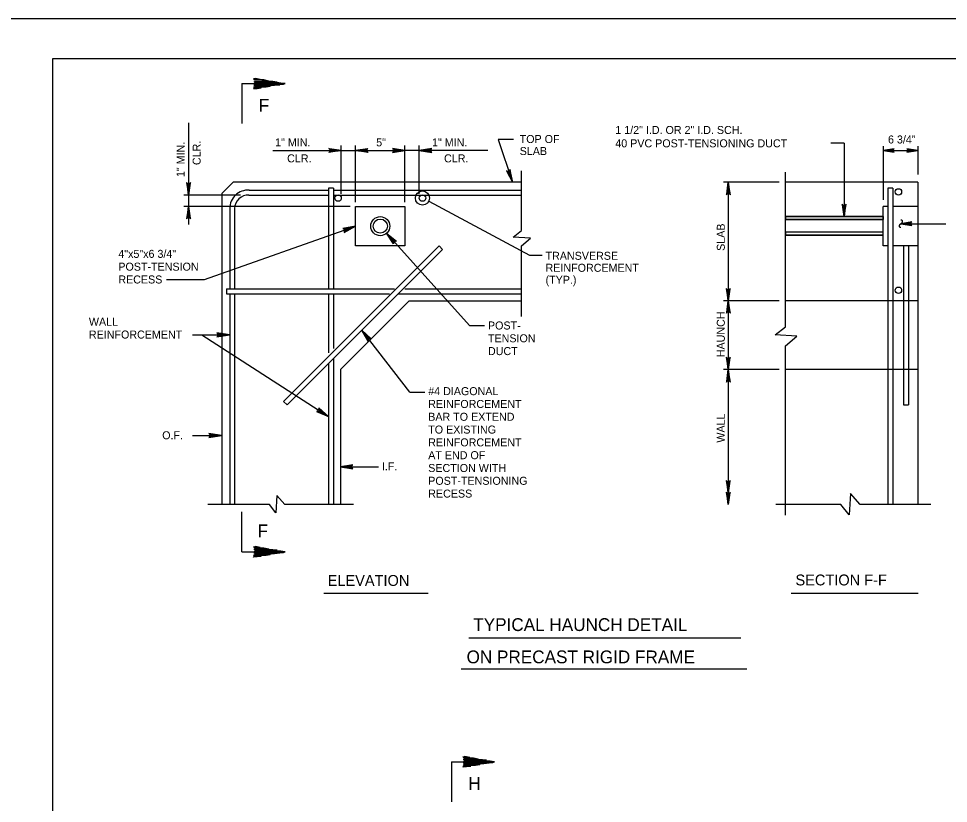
# Model space of a CAD drawing. Extents: x 641328 to 643024, y 298283 to 300065.
# Drawn here: x 642195.6 to 642544.1, y 299771.1 to 300065.3 of the extents above; entities that cross this region are included whole.
import ezdxf

# ---------------------------------------------------------------- set-up
doc = ezdxf.new("R2010")
doc.units = 0
for name, color, linetype in [('2', 7, 'Continuous'), ('63', 7, 'Continuous'), ('Default', 7, 'Continuous'), ('PLT-BNDY', 7, 'Continuous'), ('S-ANNO-DIMENSION-PROP', 7, 'Continuous')]:
    doc.layers.add(name, color=color, linetype=linetype)

msp = doc.modelspace()

# ---------------------------------------------------------------- linework, layer by layer
at = {"layer": '2'}
for p, q in [((642208.51, 299486.3), (642208.51, 300050.3)), ((642208.51, 300050.3), (642994.5, 300050.3)), ((642279.3, 300040.96), (642279.3, 300025.93)), ((642279.3, 300040.96), (642294.33, 300040.96)), ((642375.35, 300020.03), (642380.68, 300003.92)), ((642316.56, 299999.64), (642316.56, 300017.73)), ((642321.92, 299996.47), (642321.92, 300017.73)), ((642340.43, 299996.47), (642340.43, 300017.73)), ((642345.78, 299999.64), (642345.78, 300017.73)), ((642505, 300018.56), (642499.99, 300018.56)), ((642519.63, 300015.85), (642532.63, 300015.85)), ((642384.07, 299985.85), (642384.07, 300008.18)), ((642483.06, 299949.79), (642483.06, 300007.67)), ((642383.93, 300003.92), (642276, 300003.92)), ((642480.62, 300003.92), (642459.79, 300003.92)), ((642532.63, 300003.92), (642483.06, 300003.92)), ((642532.63, 300003.92), (642532.63, 299883.1)), ((642278.78, 299999.14), (642257.52, 299999.14)), ((642271.81, 299999.73), (642271.81, 299883.2)), ((642281.94, 299999.14), (642311.75, 299999.14)), ((642282.06, 300000.99), (642311.75, 300000.99)), ((642313.6, 300001.79), (642311.75, 300001.79)), ((642311.75, 300001.79), (642311.75, 299964.24)), ((642313.6, 300001.79), (642313.6, 299964.13)), ((642313.6, 300000.99), (642383.93, 300000.99)), ((642313.6, 299999.14), (642383.93, 299999.14)), ((642523.29, 300001.79), (642521.44, 300001.79)), ((642521.44, 300001.79), (642521.44, 299883.1)), ((642523.29, 300001.79), (642523.29, 299883.1)), ((642349.39, 299996.89), (642387.06, 299976.65)), ((642319.93, 299994.9), (642257.52, 299994.9)), ((642274.74, 299994.1), (642274.74, 299963.94)), ((642276.59, 299994.1), (642276.59, 299963.94)), ((642519.63, 299980.08), (642519.63, 299994.9)), ((642521.44, 299994.9), (642519.63, 299994.9)), ((642532.63, 299994.9), (642523.29, 299994.9)), ((642519.63, 299991.06), (642483.06, 299991.06)), ((642519.63, 299989.95), (642483.06, 299989.95)), ((642526.27, 299988.4), (642543.14, 299988.4)), ((642265.29, 299967.54), (642321.92, 299987.49)), ((642519.63, 299985.23), (642483.06, 299985.23)), ((642364.57, 299950.22), (642333.56, 299984.83)), ((642519.63, 299984.11), (642483.06, 299984.11)), ((642354.54, 299978.77), (642296.22, 299920.45)), ((642353.23, 299980.08), (642306.4, 299933.26)), ((642354.54, 299978.77), (642353.23, 299980.08)), ((642384.07, 299953.63), (642384.07, 299980.06)), ((642521.44, 299980.08), (642519.63, 299980.08)), ((642532.63, 299980.08), (642523.29, 299980.08)), ((642527.27, 299980.08), (642527.27, 299920.45)), ((642529.12, 299980.08), (642529.12, 299920.45)), ((642387.06, 299976.65), (642391.88, 299976.65)), ((642251.08, 299967.54), (642265.29, 299967.54)), ((642273.6, 299963.94), (642273.6, 299962.09)), ((642273.6, 299963.94), (642336.52, 299963.94)), ((642340.36, 299963.94), (642383.93, 299963.94)), ((642273.6, 299962.09), (642334.59, 299962.09)), ((642274.74, 299962.09), (642274.74, 299883.2)), ((642276.59, 299962.09), (642276.59, 299883.2)), ((642311.75, 299961.91), (642311.75, 299939.99)), ((642313.6, 299962.02), (642313.6, 299941.62)), ((642338, 299962.09), (642383.93, 299962.09)), ((642342.03, 299959.48), (642316.25, 299933.7)), ((642342.03, 299959.48), (642384.07, 299959.48)), ((642480.62, 299959.48), (642459.79, 299959.48)), ((642532.63, 299959.48), (642483.06, 299959.48)), ((642364.57, 299950.22), (642370.21, 299950.22)), ((642260.77, 299946.73), (642274.74, 299946.73)), ((642264.26, 299946.73), (642311.75, 299916.09)), ((642342.2, 299925.28), (642324.24, 299948.47)), ((642483.06, 299879.16), (642483.06, 299942.68)), ((642313.6, 299937.77), (642313.6, 299883.2)), ((642294.91, 299921.76), (642306.4, 299933.26)), ((642311.75, 299935.85), (642311.75, 299883.2)), ((642316.25, 299933.7), (642316.25, 299883.2)), ((642480.62, 299933.7), (642459.79, 299933.7)), ((642532.63, 299933.7), (642483.06, 299933.7)), ((642342.2, 299925.28), (642347.84, 299925.28)), ((642296.22, 299920.45), (642294.91, 299921.76)), ((642260.77, 299908.99), (642271.81, 299908.99)), ((642316.25, 299897.31), (642330.5, 299897.31)), ((642289.6, 299883.1), (642266.57, 299883.1)), ((642279.3, 299865.34), (642279.3, 299880.37)), ((642321.1, 299883.1), (642295.39, 299883.1)), ((642503.84, 299883.1), (642479.45, 299883.1)), ((642537.48, 299883.1), (642510.99, 299883.1)), ((642279.3, 299865.34), (642294.33, 299865.34)), ((642349.08, 299849.76), (642310.05, 299849.76)), ((642532.77, 299849.76), (642485.16, 299849.76)), ((642364.3, 299833.15), (642466.25, 299833.15)), ((642361.48, 299821.51), (642468.57, 299821.51)), ((642357.81, 299786.73), (642357.81, 299771.7)), ((642357.81, 299786.73), (642372.84, 299786.73))]:
    msp.add_line(p, q, dxfattribs=at)
for points in [[(642283.61, 300042.89), (642295.49, 300040.91), (642283.61, 300038.93), (642283.8, 300039.12), (642284.99, 300039.12), (642286.58, 300039.32), (642283.8, 300039.32), (642284, 300039.72), (642288.36, 300039.72), (642289.94, 300039.92), (642284, 300039.92), (642284, 300040.31), (642291.53, 300040.31), (642293.51, 300040.51), (642284, 300040.51), (642284, 300040.71), (642294.89, 300040.71), (642295.49, 300040.91), (642293.9, 300041.1), (642284.2, 300041.1), (642284, 300041.3), (642292.52, 300041.5), (642290.93, 300041.7), (642284, 300041.7), (642284, 300041.9), (642289.35, 300041.9), (642287.57, 300042.29), (642284, 300042.29), (642283.8, 300042.49), (642286.18, 300042.49), (642284.4, 300042.89), (642283.8, 300042.69)], [(642523.55, 300016.35), (642523.4, 300016.06), (642519.63, 300015.85), (642523.55, 300016.35), (642523.75, 300016.52), (642519.63, 300015.85), (642523.4, 300015.67), (642523.54, 300015.39), (642519.63, 300015.85), (642523.75, 300015.2), (642523.54, 300015.39)], [(642528.7, 300015.36), (642528.85, 300015.65), (642532.63, 300015.85), (642528.7, 300015.36), (642528.5, 300015.19), (642532.63, 300015.85), (642528.85, 300016.04), (642528.72, 300016.32), (642532.63, 300015.85), (642528.5, 300016.51), (642528.72, 300016.32)], [(642378.68, 300008.12), (642379.05, 300008.06), (642380.68, 300003.92), (642378.68, 300008.12), (642378.42, 300008.28), (642380.68, 300003.92), (642379.5, 300008.21), (642379.76, 300008.46), (642380.68, 300003.92), (642379.89, 300008.77), (642379.76, 300008.46)], [(642530.19, 299988.89), (642530.04, 299988.6), (642526.27, 299988.4), (642530.19, 299988.89), (642530.39, 299989.06), (642526.27, 299988.4), (642530.04, 299988.21), (642530.18, 299987.93), (642526.27, 299988.4), (642530.39, 299987.74), (642530.18, 299987.93)], [(642317.76, 299985.4), (642317.81, 299985.77), (642321.92, 299987.49), (642317.76, 299985.4), (642317.61, 299985.13), (642321.92, 299987.49), (642317.66, 299986.21), (642317.4, 299986.46), (642321.92, 299987.49), (642317.09, 299986.59), (642317.4, 299986.46)], [(642270.12, 299946.15), (642270.29, 299946.48), (642274.74, 299946.73), (642270.12, 299946.15), (642269.89, 299945.95), (642274.74, 299946.73), (642270.3, 299946.95), (642270.14, 299947.28), (642274.74, 299946.73), (642269.89, 299947.5), (642270.14, 299947.28)], [(642307.56, 299918.11), (642307.89, 299918.29), (642311.75, 299916.09), (642307.56, 299918.11), (642307.25, 299918.06), (642311.75, 299916.09), (642308.14, 299918.68), (642308.18, 299919.05), (642311.75, 299916.09), (642308.09, 299919.37), (642308.18, 299919.05)], [(642267.19, 299908.41), (642267.37, 299908.75), (642271.81, 299908.99), (642267.19, 299908.41), (642266.96, 299908.21), (642271.81, 299908.99), (642267.37, 299909.21), (642267.21, 299909.54), (642271.81, 299908.99), (642266.96, 299909.76), (642267.21, 299909.54)], [(642283.61, 299867.37), (642295.49, 299865.39), (642283.61, 299863.41), (642283.8, 299863.61), (642284.99, 299863.61), (642286.58, 299863.81), (642283.8, 299863.81), (642284, 299864.21), (642288.36, 299864.21), (642289.94, 299864.4), (642284, 299864.4), (642284, 299864.8), (642291.53, 299864.8), (642293.51, 299865), (642284, 299865), (642284, 299865.2), (642294.89, 299865.2), (642295.49, 299865.39), (642293.9, 299865.59), (642284.2, 299865.59), (642284, 299865.79), (642292.52, 299865.99), (642290.93, 299866.19), (642284, 299866.19), (642284, 299866.38), (642289.35, 299866.38), (642287.57, 299866.78), (642284, 299866.78), (642283.8, 299866.98), (642286.18, 299866.98), (642284.4, 299867.37), (642283.8, 299867.18)], [(642362.11, 299788.65), (642373.99, 299786.67), (642362.11, 299784.69), (642362.31, 299784.89), (642363.5, 299784.89), (642365.08, 299785.09), (642362.31, 299785.09), (642362.51, 299785.48), (642366.87, 299785.48), (642368.45, 299785.68), (642362.51, 299785.68), (642362.51, 299786.08), (642370.03, 299786.08), (642372.01, 299786.28), (642362.51, 299786.28), (642362.51, 299786.47), (642373.4, 299786.47), (642373.99, 299786.67), (642372.41, 299786.87), (642362.71, 299786.87), (642362.51, 299787.07), (642371.02, 299787.27), (642369.44, 299787.46), (642362.51, 299787.46), (642362.51, 299787.66), (642367.86, 299787.66), (642366.07, 299788.06), (642362.51, 299788.06), (642362.31, 299788.26), (642364.69, 299788.26), (642362.91, 299788.65), (642362.31, 299788.45)]]:
    msp.add_lwpolyline(points, dxfattribs=at)
for points in [[(642321.92, 299994.9), (642340.43, 299994.9), (642340.43, 299980.08), (642321.92, 299980.08)], [(642519.63, 299989.95), (642483.06, 299989.95), (642483.06, 299991.06), (642519.63, 299991.06)], [(642519.63, 299991.06), (642483.06, 299991.06), (642483.06, 299989.95), (642519.63, 299989.95)], [(642519.63, 299985.23), (642483.06, 299985.23), (642483.06, 299984.11), (642519.63, 299984.11)]]:
    msp.add_lwpolyline(points, close=True, dxfattribs=at)
for centre in [(642315.36, 299998.02), (642346.99, 299998.02), (642525.36, 300000.33), (642525.36, 299963.45)]:
    msp.add_circle(centre, 1.21, dxfattribs=at)
for radius in [6.89, 5.04]:
    msp.add_arc((642281.63, 299994.1), radius, 86.4281, 180, dxfattribs=at)
at = {"layer": '63'}
for p, q in [((642259.35, 300026.25), (642259.35, 299994.9)), ((642505, 300018.56), (642505, 299991.06)), ((642519.63, 300017.46), (642519.63, 299997.36)), ((642532.63, 300017.46), (642532.63, 300006.79)), ((642290.92, 300015.9), (642321.92, 300015.9)), ((642321.92, 300015.9), (642340.43, 300015.9)), ((642371.43, 300015.9), (642340.43, 300015.9)), ((642461.61, 300003.92), (642461.61, 299959.48)), ((642259.35, 299994.9), (642259.35, 299988.14)), ((642380.96, 299983.33), (642384.04, 299985.82)), ((642387.46, 299982.98), (642380.96, 299983.33)), ((642384.07, 299980.06), (642387.46, 299982.98)), ((642461.61, 299959.48), (642461.61, 299933.7)), ((642479.21, 299946.71), (642483.01, 299949.79)), ((642487.23, 299946.29), (642479.21, 299946.71)), ((642483.06, 299942.68), (642487.23, 299946.29)), ((642461.61, 299933.7), (642461.61, 299883.1)), ((642527.27, 299920.45), (642529.12, 299920.45)), ((642507.34, 299887.32), (642506.92, 299879.3)), ((642510.99, 299883.1), (642507.34, 299887.32)), ((642292.43, 299886.52), (642292.09, 299880.02)), ((642295.39, 299883.1), (642292.43, 299886.52)), ((642292.09, 299880.02), (642289.6, 299883.1)), ((642506.92, 299879.3), (642503.84, 299883.1))]:
    msp.add_line(p, q, dxfattribs=at)
for points in [[(642312.13, 300016.45), (642312.3, 300016.13), (642316.56, 300015.9), (642312.13, 300016.45), (642311.91, 300016.65), (642316.56, 300015.9), (642312.3, 300015.69), (642312.15, 300015.37), (642316.56, 300015.9), (642311.91, 300015.16), (642312.15, 300015.37)], [(642326.34, 300015.34), (642326.18, 300015.66), (642321.92, 300015.9), (642326.34, 300015.34), (642326.57, 300015.15), (642321.92, 300015.9), (642326.18, 300016.11), (642326.33, 300016.43), (642321.92, 300015.9), (642326.57, 300016.64), (642326.33, 300016.43)], [(642336, 300015.34), (642336.17, 300015.66), (642340.43, 300015.9), (642336, 300015.34), (642335.78, 300015.15), (642340.43, 300015.9), (642336.17, 300016.11), (642336.02, 300016.43), (642340.43, 300015.9), (642335.78, 300016.64), (642336.02, 300016.43)], [(642350.21, 300016.45), (642350.05, 300016.13), (642345.78, 300015.9), (642350.21, 300016.45), (642350.44, 300016.65), (642345.78, 300015.9), (642350.04, 300015.69), (642350.2, 300015.37), (642345.78, 300015.9), (642350.44, 300015.16), (642350.2, 300015.37)], [(642258.8, 300003.57), (642259.12, 300003.4), (642259.35, 299999.14), (642258.8, 300003.57), (642258.6, 300003.79), (642259.35, 299999.14), (642259.56, 300003.4), (642259.88, 300003.55), (642259.35, 299999.14), (642260.09, 300003.79), (642259.88, 300003.55)], [(642462.17, 299999.5), (642461.85, 299999.66), (642461.61, 300003.92), (642462.17, 299999.5), (642462.37, 299999.27), (642461.61, 300003.92), (642461.4, 299999.66), (642461.09, 299999.51), (642461.61, 300003.92), (642460.88, 299999.27), (642461.09, 299999.51)], [(642504.44, 299995.49), (642504.76, 299995.32), (642505, 299991.06), (642504.44, 299995.49), (642504.25, 299995.72), (642505, 299991.06), (642505.21, 299995.32), (642505.53, 299995.48), (642505, 299991.06), (642505.74, 299995.72), (642505.53, 299995.48)], [(642259.91, 299990.47), (642259.59, 299990.63), (642259.35, 299994.9), (642259.91, 299990.47), (642260.1, 299990.24), (642259.35, 299994.9), (642259.14, 299990.64), (642258.82, 299990.48), (642259.35, 299994.9), (642258.61, 299990.24), (642258.82, 299990.48)], [(642336.11, 299981.17), (642336.24, 299981.5), (642333.56, 299984.83), (642336.11, 299981.17), (642336.12, 299980.87), (642333.56, 299984.83), (642336.57, 299981.8), (642336.91, 299981.9), (642333.56, 299984.83), (642337.22, 299981.86), (642336.91, 299981.9)], [(642461.06, 299963.91), (642461.38, 299963.75), (642461.61, 299959.48), (642461.06, 299963.91), (642460.86, 299964.14), (642461.61, 299959.48), (642461.83, 299963.74), (642462.14, 299963.9), (642461.61, 299959.48), (642462.35, 299964.14), (642462.14, 299963.9)], [(642462.17, 299955.06), (642461.85, 299955.22), (642461.61, 299959.48), (642462.17, 299955.06), (642462.37, 299954.83), (642461.61, 299959.48), (642461.4, 299955.22), (642461.09, 299955.07), (642461.61, 299959.48), (642460.88, 299954.83), (642461.09, 299955.07)], [(642327.4, 299945.32), (642327.05, 299945.26), (642324.24, 299948.47), (642327.4, 299945.32), (642327.7, 299945.27), (642324.24, 299948.47), (642326.69, 299944.99), (642326.54, 299944.67), (642324.24, 299948.47), (642326.52, 299944.35), (642326.54, 299944.67)], [(642461.06, 299938.13), (642461.38, 299937.96), (642461.61, 299933.7), (642461.06, 299938.13), (642460.86, 299938.35), (642461.61, 299933.7), (642461.83, 299937.96), (642462.14, 299938.11), (642461.61, 299933.7), (642462.35, 299938.35), (642462.14, 299938.11)], [(642462.17, 299929.27), (642461.85, 299929.43), (642461.61, 299933.7), (642462.17, 299929.27), (642462.37, 299929.04), (642461.61, 299933.7), (642461.4, 299929.44), (642461.09, 299929.28), (642461.61, 299933.7), (642460.88, 299929.04), (642461.09, 299929.28)], [(642320.68, 299897.87), (642320.51, 299897.55), (642316.25, 299897.31), (642320.68, 299897.87), (642320.9, 299898.06), (642316.25, 299897.31), (642320.51, 299897.1), (642320.66, 299896.78), (642316.25, 299897.31), (642320.9, 299896.57), (642320.66, 299896.78)], [(642461.06, 299891.95), (642461.38, 299891.79), (642461.61, 299887.53), (642461.06, 299891.95), (642460.86, 299892.18), (642461.61, 299887.53), (642461.83, 299891.79), (642462.14, 299891.94), (642461.61, 299887.53), (642462.35, 299892.18), (642462.14, 299891.94)], [(642461.06, 299887.53), (642461.38, 299887.36), (642461.61, 299883.1), (642461.06, 299887.53), (642460.86, 299887.75), (642461.61, 299883.1), (642461.83, 299887.36), (642462.14, 299887.51), (642461.61, 299883.1), (642462.35, 299887.75), (642462.14, 299887.51)]]:
    msp.add_lwpolyline(points, dxfattribs=at)
for centre, radius in [((642346.99, 299998.02), 2.65), ((642331.17, 299987.49), 3.57), ((642331.17, 299987.49), 2.65)]:
    msp.add_circle(centre, radius, dxfattribs=at)
at = {"layer": 'Default'}
for p, q in [((642381.16, 300020.03), (642375.35, 300020.03)), ((642271.81, 299999.73), (642276, 300003.92))]:
    msp.add_line(p, q, dxfattribs=at)
at = {"layer": 'PLT-BNDY'}
msp.add_lwpolyline([(642168.51, 300065.3), (643009.51, 300065.3), (643009.51, 299471.3), (642168.51, 299471.3)], close=True, dxfattribs=at)
at = {"layer": 'S-ANNO-DIMENSION-PROP'}
for q in [(642526.73, 299988.87), (642526.74, 299988.87)]:
    msp.add_line((642525.8, 299987.93), q, dxfattribs=at)
for centre, start, end in [((642526.4, 299989.24), 311.7859, 104.3183), ((642526.41, 299989.23), 311.5891, 104.1215), ((642526.13, 299987.56), 131.7859, 284.3183), ((642526.13, 299987.56), 131.5891, 284.1215)]:
    msp.add_arc(centre, 0.494, start, end, dxfattribs=at)

# ---------------------------------------------------------------- texts
at = {"layer": '2'}
for s, height, p in [('F', 4.8, (642285.62, 300030.39)), ('1 1/2" I.D. OR 2" I.D. SCH. ', 3, (642419.26, 300022.04)), ('TOP OF', 3, (642383.42, 300018.65)), ('40 PVC POST-TENSIONING DUCT', 3, (642419.26, 300017.04)), ('6 3/4"', 3, (642521.46, 300018.48)), ('SLAB', 3, (642383.42, 300014.15)), ('4"x5"x6 3/4" ', 2.9999, (642233, 299975.6)), ('TRANSVERSE', 3, (642393.11, 299974.88)), ('POST-TENSION', 2.9999, (642233, 299970.8)), ('REINFORCEMENT ', 3, (642393.11, 299970.38)), ('RECESS', 3, (642233, 299966)), ('(TYP.)', 3, (642393.11, 299965.88)), ('F', 4.8, (642285.17, 299870.87)), ('ELEVATION', 4.08, (642311.45, 299852.62)), ('SECTION F-F', 4.08, (642486.78, 299852.81)), ('TYPICAL HAUNCH DETAIL', 4.8, (642366.02, 299835.71)), ('ON PRECAST RIGID FRAME', 4.8, (642363.51, 299823.61)), ('H', 4.8, (642364.14, 299776.16))]:
    msp.add_text(s, height=height, dxfattribs=at).set_placement(p)
at = {"layer": '63'}
for s, height, p in [('1" MIN. ', 3, (642291.76, 300017.4)), ('5"', 3, (642329.63, 300017.4)), ('1" MIN. ', 3, (642350.57, 300017.4)), ('CLR.', 3, (642296.26, 300011.4)), ('CLR.', 3, (642355.07, 300011.4)), ('WALL', 3, (642221.97, 299950.15)), ('POST-', 3, (642371.53, 299948.75)), ('REINFORCEMENT', 2.9999, (642221.97, 299945.35)), ('TENSION', 3, (642371.53, 299943.95)), ('DUCT', 3, (642371.53, 299939.15)), ('#4 DIAGONAL', 2.9999, (642349.14, 299924.13)), ('REINFORCEMENT', 2.9999, (642349.14, 299919.33)), ('BAR TO EXTEND', 2.9999, (642349.14, 299914.53)), ('TO EXISTING', 2.9999, (642349.14, 299909.73)), ('O.F.', 3, (642249.44, 299907.59)), ('REINFORCEMENT', 2.9999, (642349.14, 299904.93)), ('AT END OF', 3, (642349.14, 299900.13)), ('I.F.', 3, (642331.77, 299895.94)), ('SECTION WITH', 2.9999, (642349.14, 299895.33)), ('POST-TENSIONING ', 2.9999, (642349.14, 299890.53)), ('RECESS', 3, (642349.14, 299885.73))]:
    msp.add_text(s, height=height, dxfattribs=at).set_placement(p)
for s, p in [('1" MIN. ', (642257.85, 300005.88)), ('CLR.', (642263.85, 300010.38)), ('SLAB', (642460.29, 299978.22)), ('HAUNCH', (642460.29, 299938.35)), ('WALL', (642460.29, 299906.33))]:
    msp.add_text(s, height=3, rotation=90, dxfattribs=at).set_placement(p)

doc.saveas('drawing.dxf')
